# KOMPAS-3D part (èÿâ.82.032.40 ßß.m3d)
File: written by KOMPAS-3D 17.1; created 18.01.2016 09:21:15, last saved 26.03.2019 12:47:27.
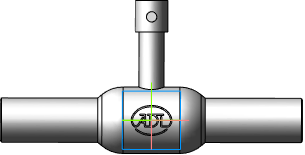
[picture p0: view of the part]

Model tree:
1. Операция без истории:5  (labels: Сталь 20  ГОСТ 1050-88)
